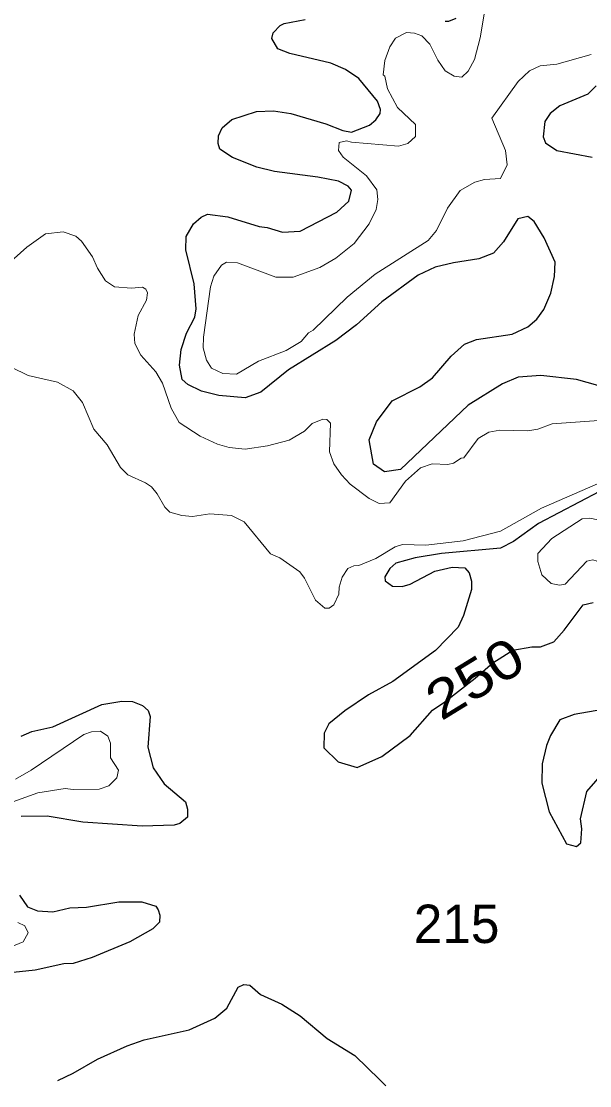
# Model space of a CAD drawing. Extents: x 763.2 to 816.8, y 7896.5 to 7952.7.
# Drawn here: x 786.395 to 788.764, y 7896.927 to 7901.365 of the extents above; entities that cross this region are included whole.
import ezdxf
from ezdxf.enums import TextEntityAlignment as Align

# ---------------------------------------------------------------- set-up
doc = ezdxf.new("R2010")
doc.units = 0
doc.header["$LTSCALE"] = 0.064
doc.layers.add('1', color=7, linetype='Continuous', lineweight=25)
doc.layers.add('2', color=7, linetype='Continuous', lineweight=13)
doc.layers.add('21', color=7, linetype='Continuous')
doc.layers.add('61', color=7, linetype='Continuous')

msp = doc.modelspace()

# ---------------------------------------------------------------- linework, layer by layer
at = {"layer": '1'}
for points in [[(788.6023, 7900.231), (788.618, 7900.3011), (788.6197, 7900.3598), (788.5739, 7900.4613), (788.5325, 7900.5297), (788.5068, 7900.5506), (788.4642, 7900.5405), (788.4054, 7900.4448), (788.3638, 7900.3983), (788.3015, 7900.3736), (788.1961, 7900.3576), (788.1207, 7900.3389), (788.0491, 7900.3064), (787.8979, 7900.1947), (787.792, 7900.0991), (787.7063, 7900.0342), (787.5084, 7899.9121), (787.3932, 7899.8183), (787.3286, 7899.7952), (787.2184, 7899.8051), (787.1463, 7899.822), (787.0893, 7899.8506), (787.0658, 7899.8712), (787.0542, 7899.9314), (787.0613, 7899.9957), (787.0832, 7900.0645), (787.1179, 7900.1312), (787.1247, 7900.1656), (787.1161, 7900.2697), (787.0805, 7900.4113), (787.0822, 7900.4679), (787.1134, 7900.5197), (787.1443, 7900.5484), (787.1708, 7900.5606), (787.2556, 7900.5495), (787.3861, 7900.5087), (787.4206, 7900.5048), (787.4834, 7900.4858), (787.5569, 7900.4899), (787.7104, 7900.5695), (787.7602, 7900.6145), (787.7718, 7900.6611), (787.7579, 7900.677), (787.7177, 7900.6979), (787.6318, 7900.7152), (787.4502, 7900.7384), (787.3763, 7900.7569), (787.275, 7900.7972), (787.2226, 7900.8313), (787.2154, 7900.8551), (787.2169, 7900.8872), (787.233, 7900.9202), (787.2729, 7900.9551), (787.3754, 7900.9882), (787.4469, 7900.9914), (787.5185, 7900.9801), (787.6638, 7900.9371), (787.7354, 7900.9095), (787.7715, 7900.903), (787.8459, 7900.9316), (787.8724, 7900.9537), (787.8907, 7900.9797), (787.8921, 7900.9971), (787.8804, 7901.0321), (787.8013, 7901.1266), (787.746, 7901.1639), (787.6851, 7901.1902), (787.5143, 7901.231), (787.4642, 7901.2493), (787.439, 7901.2922), (787.4453, 7901.3166), (787.4735, 7901.3467), (787.4908, 7901.3553), (787.5777, 7901.3726)], [(788.1612, 7901.3648), (788.1767, 7901.3646), (788.2077, 7901.3783)], [(788.7912, 7901.095), (788.7564, 7901.0601), (788.6401, 7901.0127), (788.5995, 7900.9804), (788.5777, 7900.9462), (788.5695, 7900.8826), (788.5805, 7900.8578), (788.6277, 7900.8254), (788.7741, 7900.7976)], [(788.8865, 7899.8214), (788.7091, 7899.8706), (788.5611, 7899.8886), (788.4659, 7899.8803), (788.4008, 7899.8529), (788.2572, 7899.7637), (787.9758, 7899.4964), (787.9088, 7899.4862), (787.863, 7899.5177), (787.8449, 7899.6191), (787.8759, 7899.6947), (787.9412, 7899.7829), (788.0556, 7899.8409), (788.1095, 7899.8779), (788.1865, 7899.9692), (788.2424, 7900.0184), (788.2917, 7900.0381), (788.4412, 7900.0608), (788.5059, 7900.0914), (788.5432, 7900.1224), (788.5732, 7900.1634), (788.6023, 7900.231)], [(788.8044, 7899.4038), (788.5514, 7899.2707), (788.4461, 7899.1952), (788.392, 7899.1687), (788.1463, 7899.1457), (788.0368, 7899.1274), (787.9559, 7899.1052), (787.9318, 7899.0832), (787.9105, 7899.0482), (787.9111, 7899.0321), (787.9418, 7899.0094), (787.9819, 7899.0079), (788.0158, 7899.0183), (788.1191, 7899.0723), (788.1914, 7899.0884), (788.2431, 7899.0858), (788.2624, 7899.0652), (788.2718, 7899.0301), (788.2718, 7898.9954), (788.2377, 7898.887), (788.2158, 7898.8387), (788.1217, 7898.7411), (787.9432, 7898.6118), (787.842, 7898.5562), (787.7438, 7898.4903), (787.6776, 7898.4363), (787.6573, 7898.3972), (787.6562, 7898.3351), (787.7161, 7898.2769), (787.7949, 7898.2538), (787.8972, 7898.2995), (788.016, 7898.3872), (788.1087, 7898.4927), (788.1605, 7898.5278), (788.2873, 7898.6267), (788.36, 7898.6894), (788.4435, 7898.7426), (788.5225, 7898.7563), (788.5586, 7898.7566), (788.6145, 7898.7775), (788.6582, 7898.8256), (788.7366, 7898.9315), (788.778, 7898.9419)], [(786.3952, 7898.3848), (786.4394, 7898.4039), (786.5266, 7898.4228), (786.7312, 7898.5166), (786.814, 7898.5309), (786.8592, 7898.5291), (786.9006, 7898.5117), (786.9244, 7898.491), (786.9324, 7898.4662), (786.9223, 7898.3379), (786.9454, 7898.2525), (786.9904, 7898.1856), (787.0799, 7898.1108), (787.0886, 7898.0802), (787.0875, 7898.0473), (787.0563, 7898.0207), (787.0327, 7898.0136), (786.8996, 7898.0086), (786.6513, 7898.0263), (786.5036, 7898.0513), (786.3951, 7898.0495)], [(786.3877, 7897.7216), (786.4215, 7897.6727), (786.4625, 7897.6566), (786.5266, 7897.652), (786.5982, 7897.6682), (786.6672, 7897.6717), (786.8011, 7897.6932), (786.898, 7897.693), (786.9557, 7897.6755), (786.9662, 7897.6597), (786.9728, 7897.6376), (786.971, 7897.6089), (786.9433, 7897.5809), (786.848, 7897.5267), (786.6902, 7897.4611), (786.612, 7897.4368), (786.5727, 7897.4349), (786.4526, 7897.4085), (786.3352, 7897.3957)], [(786.5475, 7896.9483), (786.6113, 7896.9795), (786.7124, 7897.0373), (786.8372, 7897.0932), (786.9078, 7897.1178), (787.0952, 7897.1606), (787.2024, 7897.2084), (787.2516, 7897.2501), (787.2991, 7897.3378), (787.323, 7897.3491), (787.3483, 7897.3465), (787.3927, 7897.3069), (787.4805, 7897.267), (787.558, 7897.2186), (787.6704, 7897.1245), (787.7854, 7897.0537), (787.889, 7896.9519), (787.9142, 7896.9271)]]:
    msp.add_lwpolyline(points, dxfattribs=at)
msp.add_lwpolyline([(788.7522, 7898.1537), (788.8275, 7898.2404), (788.8997, 7898.288), (788.9281, 7898.3148), (788.9765, 7898.3826), (788.9835, 7898.422), (788.9679, 7898.474), (788.9381, 7898.4929), (788.8183, 7898.495), (788.6993, 7898.4752), (788.6403, 7898.452), (788.6006, 7898.3866), (788.5837, 7898.3454), (788.5663, 7898.269), (788.5646, 7898.1886), (788.5947, 7898.0694), (788.6671, 7897.936), (788.7096, 7897.9238), (788.7268, 7897.9398), (788.7319, 7897.9987), (788.7257, 7898.0399)], close=True, dxfattribs=at)
at = {"layer": '2'}
for points in [[(788.3313, 7901.4363), (788.308, 7901.2954), (788.2843, 7901.2058), (788.2582, 7901.1569), (788.2318, 7901.1313), (788.1986, 7901.1363), (788.1624, 7901.1587), (788.1313, 7901.2023), (788.0973, 7901.2688), (788.0641, 7901.3038), (788.0345, 7901.3152), (788.0003, 7901.3184), (787.9551, 7901.2942), (787.9315, 7901.2585), (787.9109, 7901.2017), (787.9039, 7901.1416), (787.9102, 7901.1354), (787.9216, 7901.0825), (787.9634, 7901.0046), (788.0379, 7900.9344), (788.0385, 7900.8836), (788.0056, 7900.8552), (787.9667, 7900.844), (787.772, 7900.86), (787.7504, 7900.8666), (787.72, 7900.8595), (787.7166, 7900.8262), (787.737, 7900.7982), (787.8341, 7900.7206), (787.8774, 7900.6619), (787.8806, 7900.621), (787.8744, 7900.5803), (787.8446, 7900.5198), (787.7832, 7900.4388), (787.7066, 7900.3768), (787.6394, 7900.3383), (787.5282, 7900.2985), (787.456, 7900.2981), (787.2957, 7900.357), (787.2505, 7900.3603), (787.2294, 7900.3482), (787.1983, 7900.3018), (787.1841, 7900.2575), (787.1541, 7900.0472), (787.153, 7900.0031), (787.1678, 7899.9522), (787.188, 7899.9181), (787.2346, 7899.8966), (787.2923, 7899.8939), (787.3845, 7899.9477), (787.4988, 7899.9921), (787.5612, 7900.0298), (787.5926, 7900.0656), (787.6114, 7900.0765), (787.7527, 7900.2139), (787.8704, 7900.3103), (788.0906, 7900.4503), (788.1259, 7900.4925), (788.1712, 7900.5852), (788.2242, 7900.6587)], [(788.4128, 7900.826), (788.3563, 7900.9604), (788.4664, 7901.1135), (788.5132, 7901.1583), (788.5579, 7901.1787), (788.6269, 7901.1854), (788.7705, 7901.2262)], [(788.2242, 7900.6587), (788.2857, 7900.6941), (788.3252, 7900.7054), (788.3921, 7900.7094), (788.4196, 7900.7665), (788.4128, 7900.826)], [(787.8457, 7899.3751), (787.7663, 7899.4346), (787.7291, 7899.4736), (787.6971, 7899.5199), (787.68, 7899.5691), (787.6835, 7899.6887), (787.6685, 7899.7044), (787.6518, 7899.7056), (787.607, 7899.6877), (787.5755, 7899.6561), (787.5119, 7899.619), (787.4213, 7899.5948), (787.3287, 7899.5814), (787.261, 7899.5877), (787.2135, 7899.6011), (787.1413, 7899.6348), (787.0529, 7899.6917), (787.0199, 7899.7524), (786.9834, 7899.8558), (786.9561, 7899.903), (786.894, 7899.9728), (786.8685, 7900.0208), (786.8653, 7900.0603), (786.883, 7900.1378), (786.9177, 7900.2016), (786.921, 7900.2326), (786.914, 7900.2481), (786.9004, 7900.2566), (786.8546, 7900.252), (786.7843, 7900.2573), (786.7467, 7900.2823), (786.7124, 7900.3358), (786.6916, 7900.383), (786.6465, 7900.4485), (786.6224, 7900.4685), (786.5701, 7900.4871), (786.4964, 7900.4788), (786.4188, 7900.4232), (786.3135, 7900.3278)], [(786.3536, 7899.9222), (786.4246, 7899.8881), (786.5456, 7899.8608), (786.612, 7899.8245), (786.6497, 7899.775), (786.6979, 7899.6645), (786.7537, 7899.5988), (786.8081, 7899.5038)], [(788.8216, 7899.7015), (788.6079, 7899.6865), (788.5474, 7899.6635), (788.5068, 7899.6571), (788.3902, 7899.6602), (788.3442, 7899.652), (788.2993, 7899.625), (788.2393, 7899.5442), (788.2279, 7899.5432), (788.1968, 7899.5225), (788.1733, 7899.5174), (788.108, 7899.5194)], [(788.108, 7899.5194), (788.059, 7899.5026), (787.9971, 7899.4476), (787.9313, 7899.3566), (787.8868, 7899.3547), (787.8457, 7899.3751)], [(786.8081, 7899.5038), (786.8393, 7899.4743), (786.9131, 7899.4407), (786.9377, 7899.4233), (786.9613, 7899.3949), (786.9938, 7899.3384)], [(786.9938, 7899.3384), (787.0149, 7899.3188), (787.0649, 7899.3038), (787.1091, 7899.3005), (787.1814, 7899.3119), (787.2708, 7899.3047), (787.3244, 7899.2778), (787.4332, 7899.1447), (787.4727, 7899.1277), (787.5558, 7899.0697), (787.5754, 7899.0431), (787.6217, 7898.9514), (787.6607, 7898.9177), (787.6782, 7898.918), (787.6971, 7898.9313), (787.7191, 7898.9768), (787.7205, 7899.005), (787.7332, 7899.0476), (787.7564, 7899.0831), (787.7808, 7899.0946), (787.8017, 7899.0952), (787.8728, 7899.1255), (787.9532, 7899.1736), (787.9846, 7899.1836), (788.0806, 7899.1804), (788.2368, 7899.1992), (788.3924, 7899.2391), (788.5638, 7899.3345), (788.8602, 7899.4646)], [(786.2393, 7898.0671), (786.4641, 7898.1481), (786.5786, 7898.1662), (786.6114, 7898.1615), (786.7197, 7898.1639), (786.7599, 7898.1779), (786.7936, 7898.2113), (786.8008, 7898.2428), (786.767, 7898.2937), (786.7665, 7898.3555), (786.7566, 7898.3844), (786.7257, 7898.4046), (786.6885, 7898.403), (786.6553, 7898.3917), (786.4367, 7898.2423), (786.3715, 7898.2056)], [(786.3202, 7897.4928), (786.4035, 7897.5267), (786.4244, 7897.5641), (786.4097, 7897.5941), (786.3811, 7897.6073)]]:
    msp.add_lwpolyline(points, dxfattribs=at)
msp.add_lwpolyline([(788.752, 7899.1143), (788.7765, 7899.1196), (788.795, 7899.1133), (788.8404, 7899.0637), (788.889, 7898.9843), (788.9343, 7898.9374), (788.9751, 7898.9242), (788.9947, 7898.936), (789.0077, 7898.9565), (789.0131, 7898.992), (789.0113, 7899.0505), (788.9758, 7899.1675), (788.9452, 7899.2267), (788.8838, 7899.2682), (788.7643, 7899.2937), (788.7326, 7899.2905), (788.6065, 7899.2078), (788.5482, 7899.1452), (788.5481, 7899.1131), (788.5641, 7899.057), (788.6034, 7899.0213), (788.6387, 7899.0145), (788.662, 7899.0175)], close=True, dxfattribs=at)

# ---------------------------------------------------------------- texts
at = {"layer": '21'}
msp.add_text('215', height=0.16, dxfattribs=at).set_placement((788.0309, 7897.522))
at = {"layer": '61', "width": 1.2}
msp.add_text('250', height=0.16, rotation=31.576, dxfattribs=at).set_placement((788.3274, 7898.5574), align=Align.CENTER)

doc.saveas('drawing.dxf')
